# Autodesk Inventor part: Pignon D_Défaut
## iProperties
Shininess: 64.0
Length Units: 11269
Angle Units: 11279
Time Units: 11290
Mass Units: 11283
Length Display Precision: 3
Angle Display Precision: 2
Compacted: True
Part Number: Pignon D_Défaut
Document SubType Name: Modeling
Created: 2006-01
Material: Par défaut
Designer: Fricot
Density: 0.0
Volumn: 0.0
Area: 0.0
PropertySet Name: Model Information
Control State: 0
Master: False
Checked Out: False
Author: Fricot
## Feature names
1. Base1
